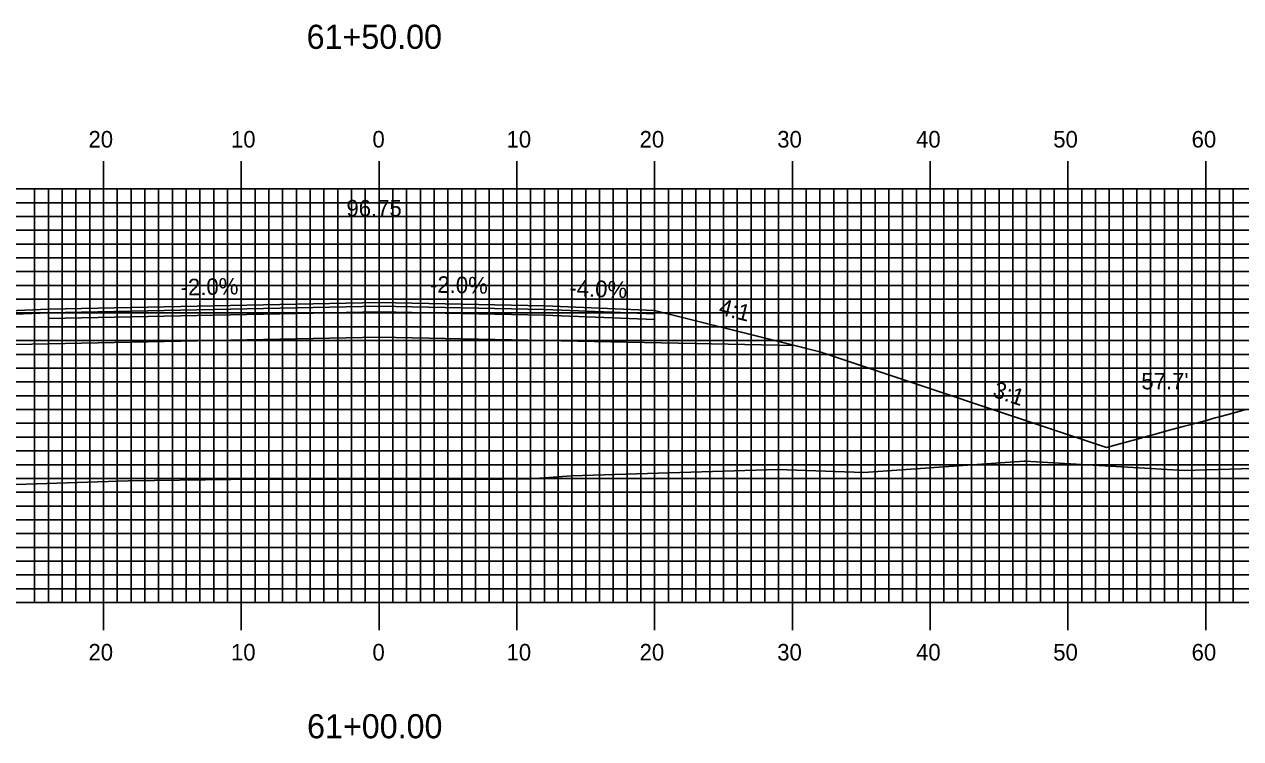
# Model space of a CAD drawing. Extents: x 1757856 to 1758199, y 442591 to 442811.
# Drawn here: x 1757995.9 to 1758084.2, y 442648.8 to 442700.6 of the extents above; entities that cross this region are included whole.
import ezdxf

# ---------------------------------------------------------------- set-up
doc = ezdxf.new("R2010")
doc.units = 0
for name, color, linetype in [('ANNOTATION', 7, 'Continuous'), ('D_Roadway_Centerline', 7, 'Continuous'), ('D_Roadway_Centerline_Text', 7, 'Continuous'), ('D_Roadway_Edge_Shoulder', 7, 'Continuous'), ('D_Roadway_Edge_TW', 7, 'Continuous'), ('D_Roadway_Pavement', 7, 'Continuous'), ('D_Roadway_SlopeLines', 7, 'Continuous'), ('D_Roadway_SubGrade', 7, 'Continuous'), ('D_Text_Standard', 7, 'Continuous'), ('H_V ANNOTATION', 7, 'Continuous'), ('MAJOR', 7, 'Continuous'), ('MINOR', 7, 'Continuous'), ('S_Roadway_Centerline', 7, 'Continuous')]:
    doc.layers.add(name, color=color, linetype=linetype)

msp = doc.modelspace()

# ---------------------------------------------------------------- linework, layer by layer
at = {"layer": 'D_Roadway_Centerline'}
for points in [[(1757948.182, 442666.803), (1757977.622, 442676.616), (1757979.448, 442677.072), (1757989.622, 442679.616), (1757997.622, 442679.936), (1758009.622, 442680.176), (1758021.622, 442680.416), (1758033.622, 442680.176), (1758041.622, 442679.856), (1758051.796, 442677.312), (1758053.622, 442676.856), (1758074.424, 442669.922)], [(1758074.423, 442669.922), (1758075.381, 442670.182), (1758076.998, 442670.62), (1758077.042, 442670.632), (1758077.141, 442670.659), (1758077.792, 442670.834), (1758079.069, 442671.18), (1758079.971, 442671.423), (1758081.122, 442671.733), (1758081.741, 442671.9), (1758082.308, 442672.053), (1758082.792, 442672.183), (1758083.156, 442672.281), (1758084.463, 442672.632)]]:
    msp.add_lwpolyline(points, dxfattribs=at)
at = {"layer": 'D_Roadway_Edge_Shoulder'}
for points in [[(1758033.622, 442680.176), (1758041.622, 442679.856), (1758041.622, 442679.606), (1758033.622, 442679.926)], [(1757997.622, 442679.936), (1757989.622, 442679.616), (1757989.622, 442679.366), (1757997.622, 442679.686)]]:
    msp.add_lwpolyline(points, close=True, dxfattribs=at)
at = {"layer": 'D_Roadway_Edge_TW'}
for points in [[(1758009.622, 442680.176), (1757997.622, 442679.936), (1757997.622, 442679.686), (1758009.622, 442679.926)], [(1758009.622, 442679.926), (1758009.622, 442680.176), (1758021.622, 442680.416), (1758033.622, 442680.176), (1758033.622, 442679.926), (1758021.622, 442680.166)]]:
    msp.add_lwpolyline(points, close=True, dxfattribs=at)
msp.add_lwpolyline([(1758009.622, 442680.176), (1758009.622, 442679.926)], dxfattribs=at)
at = {"layer": 'D_Roadway_Pavement'}
for points in [[(1758009.622, 442679.509), (1758009.622, 442679.926), (1758021.622, 442680.166), (1758033.622, 442679.926), (1758033.622, 442679.509), (1758021.622, 442679.749)], [(1758009.622, 442679.926), (1757997.622, 442679.686), (1757997.622, 442679.269), (1758009.622, 442679.509)], [(1758033.622, 442679.926), (1758041.622, 442679.606), (1758041.622, 442679.189), (1758033.622, 442679.509)]]:
    msp.add_lwpolyline(points, close=True, dxfattribs=at)
for points in [[(1757997.622, 442679.686), (1757997.622, 442679.269)], [(1758009.622, 442679.926), (1758009.622, 442679.509)], [(1758009.622, 442679.926), (1758009.622, 442679.509)]]:
    msp.add_lwpolyline(points, dxfattribs=at)
at = {"layer": 'D_Roadway_SlopeLines'}
msp.add_lwpolyline([(1758041.622, 442679.856), (1758053.622, 442676.856), (1758074.423, 442669.922)], dxfattribs=at)
at = {"layer": 'D_Roadway_SubGrade'}
for points in [[(1757997.622, 442679.269), (1757997.622, 442679.686), (1757989.622, 442679.366), (1757989.622, 442679.616), (1757979.448, 442677.072), (1757997.622, 442677.436)], [(1758009.622, 442679.509), (1757997.622, 442679.269), (1757997.622, 442677.436), (1758009.622, 442677.676)], [(1758009.622, 442677.676), (1758009.622, 442679.509), (1758021.622, 442679.749), (1758033.622, 442679.509), (1758033.622, 442677.676), (1758021.622, 442677.916)], [(1758033.622, 442679.509), (1758041.622, 442679.189), (1758041.622, 442679.606), (1758041.622, 442679.856), (1758051.796, 442677.312), (1758033.622, 442677.676)]]:
    msp.add_lwpolyline(points, close=True, dxfattribs=at)
msp.add_lwpolyline([(1758009.622, 442679.509), (1758009.622, 442677.676)], dxfattribs=at)
at = {"layer": 'MAJOR'}
for p, q in [((1758001.622, 442690.669), (1758001.622, 442688.665)), ((1758011.622, 442690.669), (1758011.622, 442688.665)), ((1758021.622, 442690.669), (1758021.622, 442688.665)), ((1758031.622, 442690.669), (1758031.622, 442688.665)), ((1758041.622, 442690.669), (1758041.622, 442688.665)), ((1758051.622, 442690.669), (1758051.622, 442688.665)), ((1758061.622, 442690.669), (1758061.622, 442688.665)), ((1758071.622, 442690.669), (1758071.622, 442688.665)), ((1758081.622, 442690.669), (1758081.622, 442688.665)), ((1757881.622, 442688.665), (1758161.622, 442688.665)), ((1757881.622, 442688.665), (1758161.622, 442688.665)), ((1758001.622, 442658.665), (1758001.622, 442688.665)), ((1758011.622, 442658.665), (1758011.622, 442688.665)), ((1758021.622, 442658.665), (1758021.622, 442688.665)), ((1758031.622, 442658.665), (1758031.622, 442688.665)), ((1758041.622, 442658.665), (1758041.622, 442688.665)), ((1758051.622, 442658.665), (1758051.622, 442688.665)), ((1758061.622, 442658.665), (1758061.622, 442688.665)), ((1758071.622, 442658.665), (1758071.622, 442688.665)), ((1758081.622, 442658.665), (1758081.622, 442688.665)), ((1757881.622, 442683.665), (1758161.622, 442683.665)), ((1757881.622, 442678.665), (1758161.622, 442678.665)), ((1757881.622, 442673.665), (1758161.622, 442673.665)), ((1757881.622, 442668.665), (1758161.622, 442668.665)), ((1757881.622, 442663.665), (1758161.622, 442663.665)), ((1757881.622, 442658.665), (1758161.622, 442658.665)), ((1757881.622, 442658.665), (1758161.622, 442658.665)), ((1758001.622, 442656.661), (1758001.622, 442658.665)), ((1758011.622, 442656.661), (1758011.622, 442658.665)), ((1758021.622, 442656.661), (1758021.622, 442658.665)), ((1758031.622, 442656.661), (1758031.622, 442658.665)), ((1758041.622, 442656.661), (1758041.622, 442658.665)), ((1758051.622, 442656.661), (1758051.622, 442658.665)), ((1758061.622, 442656.661), (1758061.622, 442658.665)), ((1758071.622, 442656.661), (1758071.622, 442658.665)), ((1758081.622, 442656.661), (1758081.622, 442658.665))]:
    msp.add_line(p, q, dxfattribs=at)
at = {"layer": 'MINOR'}
for p, q in [((1757996.622, 442658.665), (1757996.622, 442688.665)), ((1757997.622, 442658.665), (1757997.622, 442688.665)), ((1757998.622, 442658.665), (1757998.622, 442688.665)), ((1757999.622, 442658.665), (1757999.622, 442688.665)), ((1758000.622, 442658.665), (1758000.622, 442688.665)), ((1758002.622, 442658.665), (1758002.622, 442688.665)), ((1758003.622, 442658.665), (1758003.622, 442688.665)), ((1758004.622, 442658.665), (1758004.622, 442688.665)), ((1758005.622, 442658.665), (1758005.622, 442688.665)), ((1758006.622, 442658.665), (1758006.622, 442688.665)), ((1758007.622, 442658.665), (1758007.622, 442688.665)), ((1758008.622, 442658.665), (1758008.622, 442688.665)), ((1758009.622, 442658.665), (1758009.622, 442688.665)), ((1758010.622, 442658.665), (1758010.622, 442688.665)), ((1758012.622, 442658.665), (1758012.622, 442688.665)), ((1758013.622, 442658.665), (1758013.622, 442688.665)), ((1758014.622, 442658.665), (1758014.622, 442688.665)), ((1758015.622, 442658.665), (1758015.622, 442688.665)), ((1758016.622, 442658.665), (1758016.622, 442688.665)), ((1758017.622, 442658.665), (1758017.622, 442688.665)), ((1758018.622, 442658.665), (1758018.622, 442688.665)), ((1758019.622, 442658.665), (1758019.622, 442688.665)), ((1758020.622, 442658.665), (1758020.622, 442688.665)), ((1758022.622, 442658.665), (1758022.622, 442688.665)), ((1758023.622, 442658.665), (1758023.622, 442688.665)), ((1758024.622, 442658.665), (1758024.622, 442688.665)), ((1758025.622, 442658.665), (1758025.622, 442688.665)), ((1758026.622, 442658.665), (1758026.622, 442688.665)), ((1758027.622, 442658.665), (1758027.622, 442688.665)), ((1758028.622, 442658.665), (1758028.622, 442688.665)), ((1758029.622, 442658.665), (1758029.622, 442688.665)), ((1758030.622, 442658.665), (1758030.622, 442688.665)), ((1758032.622, 442658.665), (1758032.622, 442688.665)), ((1758033.622, 442658.665), (1758033.622, 442688.665)), ((1758034.622, 442658.665), (1758034.622, 442688.665)), ((1758035.622, 442658.665), (1758035.622, 442688.665)), ((1758036.622, 442658.665), (1758036.622, 442688.665)), ((1758037.622, 442658.665), (1758037.622, 442688.665)), ((1758038.622, 442658.665), (1758038.622, 442688.665)), ((1758039.622, 442658.665), (1758039.622, 442688.665)), ((1758040.622, 442658.665), (1758040.622, 442688.665)), ((1758042.622, 442658.665), (1758042.622, 442688.665)), ((1758043.622, 442658.665), (1758043.622, 442688.665)), ((1758044.622, 442658.665), (1758044.622, 442688.665)), ((1758045.622, 442658.665), (1758045.622, 442688.665)), ((1758046.622, 442658.665), (1758046.622, 442688.665)), ((1758047.622, 442658.665), (1758047.622, 442688.665)), ((1758048.622, 442658.665), (1758048.622, 442688.665)), ((1758049.622, 442658.665), (1758049.622, 442688.665)), ((1758050.622, 442658.665), (1758050.622, 442688.665)), ((1758052.622, 442658.665), (1758052.622, 442688.665)), ((1758053.622, 442658.665), (1758053.622, 442688.665)), ((1758054.622, 442658.665), (1758054.622, 442688.665)), ((1758055.622, 442658.665), (1758055.622, 442688.665)), ((1758056.622, 442658.665), (1758056.622, 442688.665)), ((1758057.622, 442658.665), (1758057.622, 442688.665)), ((1758058.622, 442658.665), (1758058.622, 442688.665)), ((1758059.622, 442658.665), (1758059.622, 442688.665)), ((1758060.622, 442658.665), (1758060.622, 442688.665)), ((1758062.622, 442658.665), (1758062.622, 442688.665)), ((1758063.622, 442658.665), (1758063.622, 442688.665)), ((1758064.622, 442658.665), (1758064.622, 442688.665)), ((1758065.622, 442658.665), (1758065.622, 442688.665)), ((1758066.622, 442658.665), (1758066.622, 442688.665)), ((1758067.622, 442658.665), (1758067.622, 442688.665)), ((1758068.622, 442658.665), (1758068.622, 442688.665)), ((1758069.622, 442658.665), (1758069.622, 442688.665)), ((1758070.622, 442658.665), (1758070.622, 442688.665)), ((1758072.622, 442658.665), (1758072.622, 442688.665)), ((1758073.622, 442658.665), (1758073.622, 442688.665)), ((1758074.622, 442658.665), (1758074.622, 442688.665)), ((1758075.622, 442658.665), (1758075.622, 442688.665)), ((1758076.622, 442658.665), (1758076.622, 442688.665)), ((1758077.622, 442658.665), (1758077.622, 442688.665)), ((1758078.622, 442658.665), (1758078.622, 442688.665)), ((1758079.622, 442658.665), (1758079.622, 442688.665)), ((1758080.622, 442658.665), (1758080.622, 442688.665)), ((1758082.622, 442658.665), (1758082.622, 442688.665)), ((1758083.622, 442658.665), (1758083.622, 442688.665)), ((1757881.622, 442687.665), (1758161.622, 442687.665)), ((1757881.622, 442686.665), (1758161.622, 442686.665)), ((1757881.622, 442685.665), (1758161.622, 442685.665)), ((1757881.622, 442684.665), (1758161.622, 442684.665)), ((1757881.622, 442682.665), (1758161.622, 442682.665)), ((1757881.622, 442681.665), (1758161.622, 442681.665)), ((1757881.622, 442680.665), (1758161.622, 442680.665)), ((1757881.622, 442679.665), (1758161.622, 442679.665)), ((1757881.622, 442677.665), (1758161.622, 442677.665)), ((1757881.622, 442676.665), (1758161.622, 442676.665)), ((1757881.622, 442675.665), (1758161.622, 442675.665)), ((1757881.622, 442674.665), (1758161.622, 442674.665)), ((1757881.622, 442672.665), (1758161.622, 442672.665)), ((1757881.622, 442671.665), (1758161.622, 442671.665)), ((1757881.622, 442670.665), (1758161.622, 442670.665)), ((1757881.622, 442669.665), (1758161.622, 442669.665)), ((1757881.622, 442667.665), (1758161.622, 442667.665)), ((1757881.622, 442666.665), (1758161.622, 442666.665)), ((1757881.622, 442665.665), (1758161.622, 442665.665)), ((1757881.622, 442664.665), (1758161.622, 442664.665)), ((1757881.622, 442662.665), (1758161.622, 442662.665)), ((1757881.622, 442661.665), (1758161.622, 442661.665)), ((1757881.622, 442660.665), (1758161.622, 442660.665)), ((1757881.622, 442659.665), (1758161.622, 442659.665))]:
    msp.add_line(p, q, dxfattribs=at)
at = {"layer": 'S_Roadway_Centerline'}
msp.add_lwpolyline([(1757940.969, 442666.915), (1757948.628, 442666.796), (1757953.074, 442666.664), (1757972.115, 442667.029), (1757973.667, 442667.063), (1757975.849, 442667.092), (1757992.287, 442667.128), (1758003.424, 442667.496), (1758010.856, 442667.584), (1758022.25, 442667.623), (1758030.549, 442667.622), (1758032.623, 442667.636), (1758035.588, 442667.85), (1758050.543, 442668.304), (1758056.797, 442668.108), (1758068.439, 442668.922), (1758068.491, 442668.927), (1758068.525, 442668.925), (1758080.065, 442668.244), (1758097.403, 442668.753)], dxfattribs=at)

# ---------------------------------------------------------------- texts
at = {"layer": 'ANNOTATION'}
for s, rotation, p in [('-2.0%', 1.14576, (1758007.228, 442680.929)), ('-2.0%', 358.85424, (1758025.308, 442681.143)), ('-4.0%', 357.70939, (1758035.414, 442680.906)), ('4:1', 345.96376, (1758046.215, 442679.569)), ('3:1', 341.56522, (1758066.079, 442673.612))]:
    msp.add_text(s, height=1.2, rotation=rotation, dxfattribs=at).set_placement(p)
at = {"layer": 'D_Roadway_Centerline'}
for s, p in [('C', (1758021.617, 442680.416)), ('L', (1758021.622, 442680.409))]:
    msp.add_text(s, height=0.0146, dxfattribs=at).set_placement(p)
at = {"layer": 'D_Roadway_Centerline_Text'}
msp.add_text('96.75', height=1.2, dxfattribs=at).set_placement((1758019.252, 442686.664))
at = {"layer": 'D_Text_Standard'}
msp.add_text("57.7'", height=1.2, dxfattribs=at).set_placement((1758076.943, 442674.125))
at = {"layer": 'H_V ANNOTATION'}
for s, height, p in [('61+50.00', 1.75, (1758016.363, 442698.821)), ('20', 1.2, (1758000.53, 442691.665)), ('10', 1.2, (1758010.873, 442691.665)), ('0', 1.2, (1758021.14, 442691.665)), ('10', 1.2, (1758030.873, 442691.665)), ('20', 1.2, (1758040.53, 442691.665)), ('30', 1.2, (1758050.52, 442691.665)), ('40', 1.2, (1758060.594, 442691.665)), ('50', 1.2, (1758070.552, 442691.665)), ('60', 1.2, (1758080.594, 442691.665)), ('20', 1.2, (1758000.53, 442654.465)), ('10', 1.2, (1758010.873, 442654.465)), ('0', 1.2, (1758021.14, 442654.465)), ('10', 1.2, (1758030.873, 442654.465)), ('20', 1.2, (1758040.53, 442654.465)), ('30', 1.2, (1758050.52, 442654.465)), ('40', 1.2, (1758060.594, 442654.465)), ('50', 1.2, (1758070.552, 442654.465)), ('60', 1.2, (1758080.594, 442654.465)), ('61+00.00', 1.75, (1758016.395, 442648.821))]:
    msp.add_text(s, height=height, dxfattribs=at).set_placement(p)

doc.saveas('drawing.dxf')
